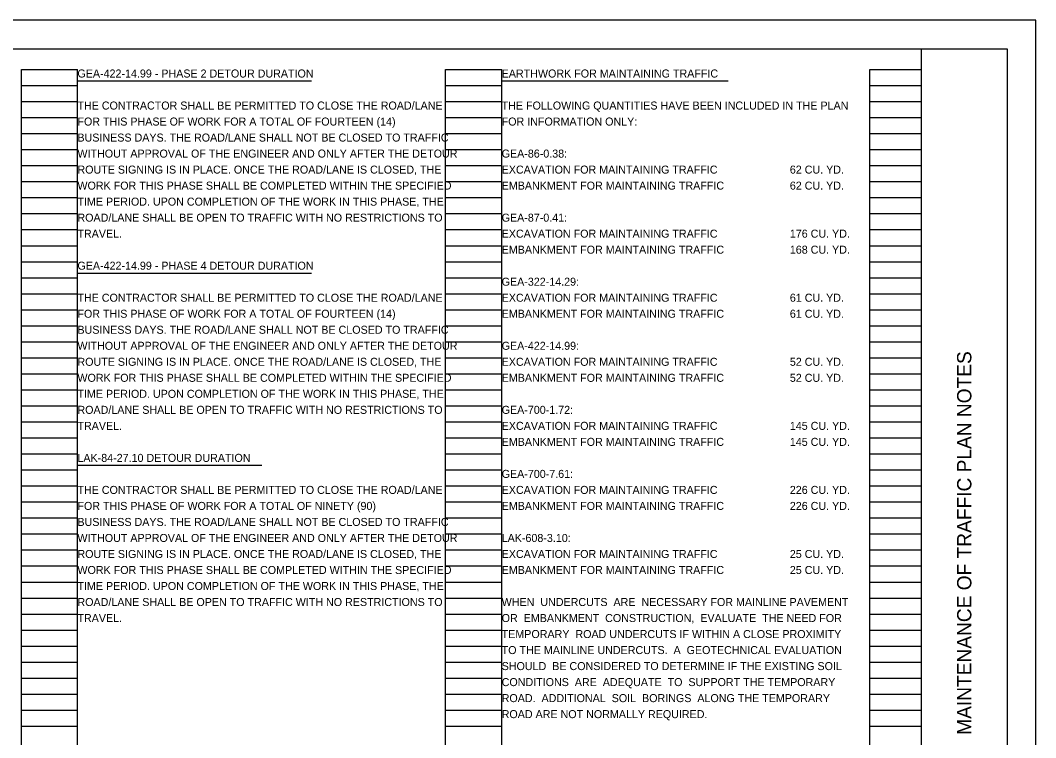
# Model space of a CAD drawing. Extents: x 0 to 34, y 0 to 22.
# Drawn here: x 16.24 to 34, y 9.46 to 22 of the extents above; entities that cross this region are included whole.
import ezdxf

# ---------------------------------------------------------------- set-up
doc = ezdxf.new("R2010")
doc.units = 0
for name, color, linetype in [('SH_Border', 7, 'Continuous'), ('SH_Cut_Line', 7, 'Continuous'), ('SH_Data', 7, 'Continuous'), ('SH_Text', 7, 'Continuous')]:
    doc.layers.add(name, color=color, linetype=linetype)

msp = doc.modelspace()

# ---------------------------------------------------------------- linework, layer by layer
at = {"layer": 'SH_Border'}
msp.add_line((32, 0.5), (32, 21.5), dxfattribs=at)
msp.add_lwpolyline([(1.5, 21.5), (33.5, 21.5), (33.5, 0.5), (1.5, 0.5)], close=True, dxfattribs=at)
at = {"layer": 'SH_Cut_Line'}
msp.add_lwpolyline([(0, 0), (34, 0), (34, 22), (0, 22)], close=True, dxfattribs=at)
at = {"layer": 'SH_Data'}
for p, q in [((16.26, 0.98), (16.26, 21.14)), ((16.26, 21.14), (17.24, 21.14)), ((17.24, 0.98), (17.24, 21.14)), ((23.68, 0.98), (23.68, 21.14)), ((23.68, 21.14), (24.66, 21.14)), ((24.66, 0.98), (24.66, 21.14)), ((31.1, 0.98), (31.1, 21.14)), ((31.1, 21.14), (32, 21.14)), ((32, 0.98), (32, 21.14)), ((16.26, 20.86), (17.24, 20.86)), ((23.68, 20.86), (24.66, 20.86)), ((31.1, 20.86), (32, 20.86)), ((16.26, 20.58), (17.24, 20.58)), ((23.68, 20.58), (24.66, 20.58)), ((31.1, 20.58), (32, 20.58)), ((16.26, 20.3), (17.24, 20.3)), ((23.68, 20.3), (24.66, 20.3)), ((31.1, 20.3), (32, 20.3)), ((16.26, 20.02), (17.24, 20.02)), ((23.68, 20.02), (24.66, 20.02)), ((31.1, 20.02), (32, 20.02)), ((16.26, 19.74), (17.24, 19.74)), ((23.68, 19.74), (24.66, 19.74)), ((31.1, 19.74), (32, 19.74)), ((16.26, 19.46), (17.24, 19.46)), ((23.68, 19.46), (24.66, 19.46)), ((31.1, 19.46), (32, 19.46)), ((16.26, 19.18), (17.24, 19.18)), ((23.68, 19.18), (24.66, 19.18)), ((31.1, 19.18), (32, 19.18)), ((16.26, 18.9), (17.24, 18.9)), ((23.68, 18.9), (24.66, 18.9)), ((31.1, 18.9), (32, 18.9)), ((16.26, 18.62), (17.24, 18.62)), ((23.68, 18.62), (24.66, 18.62)), ((31.1, 18.62), (32, 18.62)), ((16.26, 18.34), (17.24, 18.34)), ((23.68, 18.34), (24.66, 18.34)), ((31.1, 18.34), (32, 18.34)), ((16.26, 18.06), (17.24, 18.06)), ((23.68, 18.06), (24.66, 18.06)), ((31.1, 18.06), (32, 18.06)), ((16.26, 17.78), (17.24, 17.78)), ((23.68, 17.78), (24.66, 17.78)), ((31.1, 17.78), (32, 17.78)), ((16.26, 17.5), (17.24, 17.5)), ((23.68, 17.5), (24.66, 17.5)), ((31.1, 17.5), (32, 17.5)), ((16.26, 17.22), (17.24, 17.22)), ((23.68, 17.22), (24.66, 17.22)), ((31.1, 17.22), (32, 17.22)), ((16.26, 16.94), (17.24, 16.94)), ((23.68, 16.94), (24.66, 16.94)), ((31.1, 16.94), (32, 16.94)), ((16.26, 16.66), (17.24, 16.66)), ((23.68, 16.66), (24.66, 16.66)), ((31.1, 16.66), (32, 16.66)), ((16.26, 16.38), (17.24, 16.38)), ((23.68, 16.38), (24.66, 16.38)), ((31.1, 16.38), (32, 16.38)), ((16.26, 16.1), (17.24, 16.1)), ((23.68, 16.1), (24.66, 16.1)), ((31.1, 16.1), (32, 16.1)), ((16.26, 15.82), (17.24, 15.82)), ((23.68, 15.82), (24.66, 15.82)), ((31.1, 15.82), (32, 15.82)), ((16.26, 15.54), (17.24, 15.54)), ((23.68, 15.54), (24.66, 15.54)), ((31.1, 15.54), (32, 15.54)), ((16.26, 15.26), (17.24, 15.26)), ((23.68, 15.26), (24.66, 15.26)), ((31.1, 15.26), (32, 15.26)), ((16.26, 14.98), (17.24, 14.98)), ((23.68, 14.98), (24.66, 14.98)), ((31.1, 14.98), (32, 14.98)), ((16.26, 14.7), (17.24, 14.7)), ((23.68, 14.7), (24.66, 14.7)), ((31.1, 14.7), (32, 14.7)), ((16.26, 14.42), (17.24, 14.42)), ((23.68, 14.42), (24.66, 14.42)), ((31.1, 14.42), (32, 14.42)), ((16.26, 14.14), (17.24, 14.14)), ((23.68, 14.14), (24.66, 14.14)), ((31.1, 14.14), (32, 14.14)), ((16.26, 13.86), (17.24, 13.86)), ((23.68, 13.86), (24.66, 13.86)), ((31.1, 13.86), (32, 13.86)), ((16.26, 13.58), (17.24, 13.58)), ((23.68, 13.58), (24.66, 13.58)), ((31.1, 13.58), (32, 13.58)), ((16.26, 13.3), (17.24, 13.3)), ((23.68, 13.3), (24.66, 13.3)), ((31.1, 13.3), (32, 13.3)), ((16.26, 13.02), (17.24, 13.02)), ((23.68, 13.02), (24.66, 13.02)), ((31.1, 13.02), (32, 13.02)), ((16.26, 12.74), (17.24, 12.74)), ((23.68, 12.74), (24.66, 12.74)), ((31.1, 12.74), (32, 12.74)), ((16.26, 12.46), (17.24, 12.46)), ((23.68, 12.46), (24.66, 12.46)), ((31.1, 12.46), (32, 12.46)), ((16.26, 12.18), (17.24, 12.18)), ((23.68, 12.18), (24.66, 12.18)), ((31.1, 12.18), (32, 12.18)), ((16.26, 11.9), (17.24, 11.9)), ((23.68, 11.9), (24.66, 11.9)), ((31.1, 11.9), (32, 11.9)), ((16.26, 11.62), (17.24, 11.62)), ((23.68, 11.62), (24.66, 11.62)), ((31.1, 11.62), (32, 11.62)), ((16.26, 11.34), (17.24, 11.34)), ((23.68, 11.34), (24.66, 11.34)), ((31.1, 11.34), (32, 11.34)), ((16.26, 11.06), (17.24, 11.06)), ((23.68, 11.06), (24.66, 11.06)), ((31.1, 11.06), (32, 11.06)), ((16.26, 10.78), (17.24, 10.78)), ((23.68, 10.78), (24.66, 10.78)), ((31.1, 10.78), (32, 10.78)), ((16.26, 10.5), (17.24, 10.5)), ((23.68, 10.5), (24.66, 10.5)), ((31.1, 10.5), (32, 10.5)), ((16.26, 10.22), (17.24, 10.22)), ((23.68, 10.22), (24.66, 10.22)), ((31.1, 10.22), (32, 10.22)), ((16.26, 9.94), (17.24, 9.94)), ((23.68, 9.94), (24.66, 9.94)), ((31.1, 9.94), (32, 9.94)), ((16.26, 9.66), (17.24, 9.66)), ((23.68, 9.66), (24.66, 9.66)), ((31.1, 9.66), (32, 9.66))]:
    msp.add_line(p, q, dxfattribs=at)
at = {"layer": 'SH_Text'}
for p, q in [((17.24, 20.94), (21.333, 20.94)), ((24.66, 20.94), (28.621, 20.94)), ((17.24, 17.58), (21.333, 17.58)), ((17.24, 14.22), (20.463, 14.22))]:
    msp.add_line(p, q, dxfattribs=at)

# ---------------------------------------------------------------- texts
at = {"layer": 'SH_Data'}
msp.add_text('MAINTENANCE OF TRAFFIC PLAN NOTES', height=0.25, rotation=90, dxfattribs=at).set_placement((32.875, 9.509))
at = {"layer": 'SH_Text'}
for s, p in [('GEA-422-14.99 - PHASE 2 DETOUR DURATION', (17.24, 21)), ('EARTHWORK FOR MAINTAINING TRAFFIC', (24.66, 21)), ('THE CONTRACTOR SHALL BE PERMITTED TO CLOSE THE ROAD/LANE', (17.24, 20.44)), ('THE FOLLOWING QUANTITIES HAVE BEEN INCLUDED IN THE PLAN', (24.66, 20.44)), ('FOR THIS PHASE OF WORK FOR A TOTAL OF FOURTEEN (14)', (17.24, 20.16)), ('FOR INFORMATION ONLY:', (24.66, 20.16)), ('BUSINESS DAYS. THE ROAD/LANE SHALL NOT BE CLOSED TO TRAFFIC', (17.24, 19.88)), ('WITHOUT APPROVAL OF THE ENGINEER AND ONLY AFTER THE DETOUR', (17.24, 19.6)), ('GEA-86-0.38:', (24.66, 19.6)), ('ROUTE SIGNING IS IN PLACE. ONCE THE ROAD/LANE IS CLOSED, THE', (17.24, 19.32)), ('EXCAVATION FOR MAINTAINING TRAFFIC', (24.66, 19.32)), ('62 CU. YD.', (29.7, 19.32)), ('WORK FOR THIS PHASE SHALL BE COMPLETED WITHIN THE SPECIFIED', (17.24, 19.04)), ('EMBANKMENT FOR MAINTAINING TRAFFIC', (24.66, 19.04)), ('62 CU. YD.', (29.7, 19.04)), ('TIME PERIOD. UPON COMPLETION OF THE WORK IN THIS PHASE, THE', (17.24, 18.76)), ('ROAD/LANE SHALL BE OPEN TO TRAFFIC WITH NO RESTRICTIONS TO', (17.24, 18.48)), ('GEA-87-0.41:', (24.66, 18.48)), ('TRAVEL.', (17.24, 18.2)), ('EXCAVATION FOR MAINTAINING TRAFFIC', (24.66, 18.2)), ('176 CU. YD.', (29.7, 18.2)), ('EMBANKMENT FOR MAINTAINING TRAFFIC', (24.66, 17.92)), ('168 CU. YD.', (29.7, 17.92)), ('GEA-422-14.99 - PHASE 4 DETOUR DURATION', (17.24, 17.64)), ('GEA-322-14.29:', (24.66, 17.36)), ('THE CONTRACTOR SHALL BE PERMITTED TO CLOSE THE ROAD/LANE', (17.24, 17.08)), ('EXCAVATION FOR MAINTAINING TRAFFIC', (24.66, 17.08)), ('61 CU. YD.', (29.7, 17.08)), ('FOR THIS PHASE OF WORK FOR A TOTAL OF FOURTEEN (14)', (17.24, 16.8)), ('EMBANKMENT FOR MAINTAINING TRAFFIC', (24.66, 16.8)), ('61 CU. YD.', (29.7, 16.8)), ('BUSINESS DAYS. THE ROAD/LANE SHALL NOT BE CLOSED TO TRAFFIC', (17.24, 16.52)), ('WITHOUT APPROVAL OF THE ENGINEER AND ONLY AFTER THE DETOUR', (17.24, 16.24)), ('GEA-422-14.99:', (24.66, 16.24)), ('ROUTE SIGNING IS IN PLACE. ONCE THE ROAD/LANE IS CLOSED, THE', (17.24, 15.96)), ('EXCAVATION FOR MAINTAINING TRAFFIC', (24.66, 15.96)), ('52 CU. YD.', (29.7, 15.96)), ('WORK FOR THIS PHASE SHALL BE COMPLETED WITHIN THE SPECIFIED', (17.24, 15.68)), ('EMBANKMENT FOR MAINTAINING TRAFFIC', (24.66, 15.68)), ('52 CU. YD.', (29.7, 15.68)), ('TIME PERIOD. UPON COMPLETION OF THE WORK IN THIS PHASE, THE', (17.24, 15.4)), ('ROAD/LANE SHALL BE OPEN TO TRAFFIC WITH NO RESTRICTIONS TO', (17.24, 15.12)), ('GEA-700-1.72:', (24.66, 15.12)), ('TRAVEL.', (17.24, 14.84)), ('EXCAVATION FOR MAINTAINING TRAFFIC', (24.66, 14.84)), ('145 CU. YD.', (29.7, 14.84)), ('EMBANKMENT FOR MAINTAINING TRAFFIC', (24.66, 14.56)), ('145 CU. YD.', (29.7, 14.56)), ('LAK-84-27.10 DETOUR DURATION', (17.24, 14.28)), ('GEA-700-7.61:', (24.66, 14)), ('THE CONTRACTOR SHALL BE PERMITTED TO CLOSE THE ROAD/LANE', (17.24, 13.72)), ('EXCAVATION FOR MAINTAINING TRAFFIC', (24.66, 13.72)), ('226 CU. YD.', (29.7, 13.72)), ('FOR THIS PHASE OF WORK FOR A TOTAL OF NINETY (90)', (17.24, 13.44)), ('EMBANKMENT FOR MAINTAINING TRAFFIC', (24.66, 13.44)), ('226 CU. YD.', (29.7, 13.44)), ('BUSINESS DAYS. THE ROAD/LANE SHALL NOT BE CLOSED TO TRAFFIC', (17.24, 13.16)), ('WITHOUT APPROVAL OF THE ENGINEER AND ONLY AFTER THE DETOUR', (17.24, 12.88)), ('LAK-608-3.10:', (24.66, 12.88)), ('ROUTE SIGNING IS IN PLACE. ONCE THE ROAD/LANE IS CLOSED, THE', (17.24, 12.6)), ('EXCAVATION FOR MAINTAINING TRAFFIC', (24.66, 12.6)), ('25 CU. YD.', (29.7, 12.6)), ('WORK FOR THIS PHASE SHALL BE COMPLETED WITHIN THE SPECIFIED', (17.24, 12.32)), ('EMBANKMENT FOR MAINTAINING TRAFFIC', (24.66, 12.32)), ('25 CU. YD.', (29.7, 12.32)), ('TIME PERIOD. UPON COMPLETION OF THE WORK IN THIS PHASE, THE', (17.24, 12.04)), ('ROAD/LANE SHALL BE OPEN TO TRAFFIC WITH NO RESTRICTIONS TO', (17.24, 11.76)), ('WHEN  UNDERCUTS  ARE  NECESSARY FOR MAINLINE PAVEMENT', (24.66, 11.76)), ('TRAVEL.', (17.24, 11.48)), ('OR  EMBANKMENT  CONSTRUCTION,  EVALUATE  THE NEED FOR', (24.66, 11.48)), ('TEMPORARY  ROAD UNDERCUTS IF WITHIN A CLOSE PROXIMITY', (24.66, 11.2)), ('TO THE MAINLINE UNDERCUTS.  A  GEOTECHNICAL EVALUATION', (24.66, 10.92)), ('SHOULD  BE CONSIDERED TO DETERMINE IF THE EXISTING SOIL', (24.66, 10.64)), ('CONDITIONS  ARE  ADEQUATE  TO  SUPPORT THE TEMPORARY', (24.66, 10.36)), ('ROAD.  ADDITIONAL  SOIL  BORINGS  ALONG THE TEMPORARY', (24.66, 10.08)), ('ROAD ARE NOT NORMALLY REQUIRED.', (24.66, 9.8))]:
    msp.add_text(s, height=0.14, dxfattribs=at).set_placement(p)

doc.saveas('drawing.dxf')
